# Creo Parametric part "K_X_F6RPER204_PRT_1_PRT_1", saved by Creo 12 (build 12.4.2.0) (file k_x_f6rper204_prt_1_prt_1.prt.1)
Units: Custom; MM, KILOGRAM, SECS

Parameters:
  PTC_WM_ITERATION = "0"
  PTC_WM_VERSION = "-.0"
  PTC_WM_LIFECYCLE_STATE = "In Work"
  PTC_WM_LIFECYCLE = "MO_CADDocument"
  PTC_WM_CREATED_BY = "Maximilian Roepper (Z0017RMS: MO)"
  PTC_WM_CREATED_ON = "18-Sep-26 11:36:42 AM"
  PTC_WM_MODIFIED_BY = "Maximilian Roepper (Z0017RMS: MO)"
  PTC_WM_MODIFIED_ON = "18-Sep-26 11:36:46 AM"
  PDMLINKNUMBER = "PDM000071455110"
  PTC_WM_NAME = "k_x_f6rper204_prt_1_prt_1.prt"
  PTC_WM_NUMBER = "PDM000071455110"

Other parameters: WEIGHT, WEIGHT_FACTOR, WEIGHT_ADD, _MASS_TEMP, _DIFF_TEMP, MC_ERRORS, SUPPLIER

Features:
  1. coordinate system
  2. datum plane "PRT_YZ"
  3. datum plane "PRT_XY"
  4. datum plane "PRT_XZ"
  5. coordinate system
  6. datum axis
  7. datum axis
  8. datum axis
  9. coordinate system
  10. imported feature
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
Other named items: PRT, SIEMENS_MO, DRW_VIEW_ORG, PRT_X, PRT_Y, PRT_Z, CS0, ROUGH_GROB

Layers: 00_STD_CSYS-KSYS, 01_STD_PLANES-EBENEN, 02_STD_AXES-ACHSEN, 03_STD_CSYS-KSYS, 24_IMPORT_FEAT-IMPORT_KE

Surfaces: 24 tabulated cylinder, 11 plane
